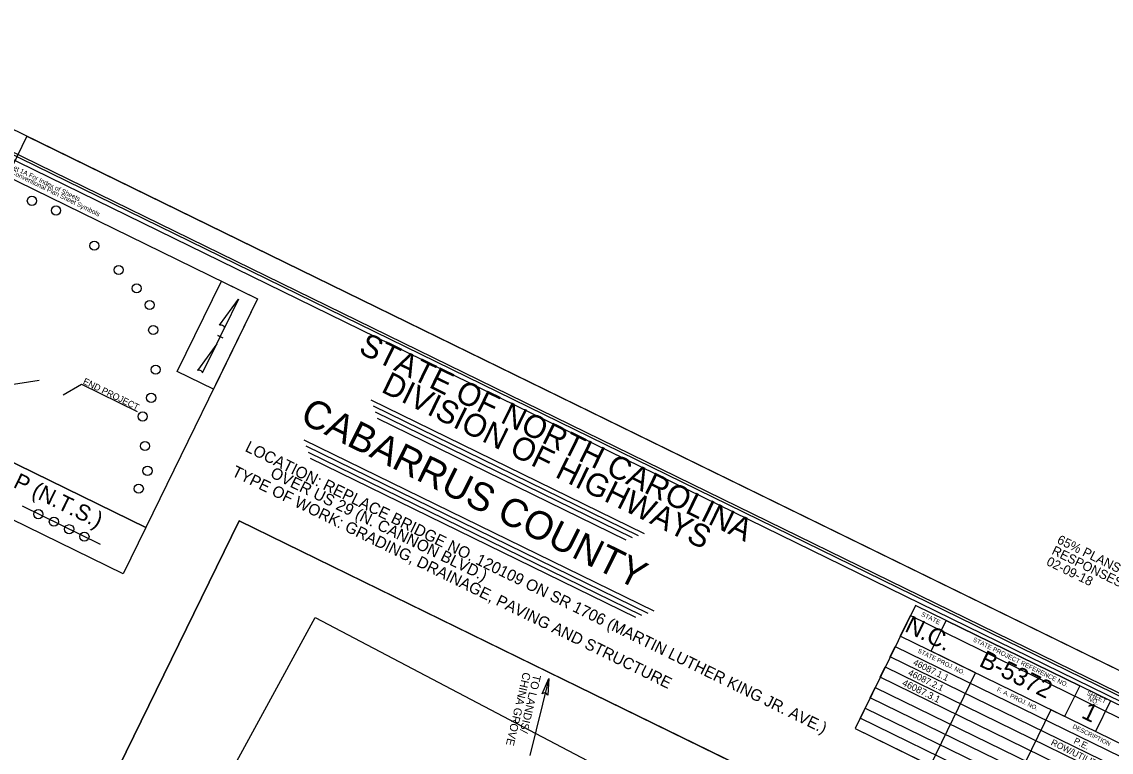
# Model space of a CAD drawing. Extents: x 1517888 to 1526099, y 633375 to 640181.
# Drawn here: x 1519355 to 1521738, y 638583 to 640181 of the extents above; entities that cross this region are included whole.
import ezdxf

# ---------------------------------------------------------------- set-up
doc = ezdxf.new("R2010")
doc.units = 0
for name, color, linetype in [('Default', 7, 'Continuous'), ('Prop North Arrow for Plan Sheets CELL', 7, 'Continuous'), ('Prop Terminator CELL', 7, 'Continuous'), ('Scratch_Level_0', 7, 'Continuous'), ('Sheet Clip Boundary CELL', 7, 'Continuous'), ('Sheet Cutting Line CELL', 7, 'Continuous'), ('Sheet Data Field CELL', 7, 'Continuous'), ('Sheet Plot Border Inside CELL', 7, 'Continuous'), ('Sheet Plot Border Outside CELL', 7, 'Continuous'), ('Sheet Title CELL', 7, 'Continuous')]:
    doc.layers.add(name, color=color, linetype=linetype)

msp = doc.modelspace()

# ---------------------------------------------------------------- linework, layer by layer
at = {"layer": 'Prop North Arrow for Plan Sheets CELL'}
for p, q in [((1519787.8, 639517.2), (1519829.4, 639574.3)), ((1519829.4, 639574.3), (1519797.9, 639509.8)), ((1519829.4, 639574.3), (1519829.4, 639574.3)), ((1519829.4, 639574.3), (1519829.4, 639574.3)), ((1519781.6, 639476.4), (1519798.9, 639511.7)), ((1519797.9, 639509.8), (1519798.8, 639511.7)), ((1519783.9, 639494.7), (1519783.8, 639494.7)), ((1519783.9, 639494.7), (1519794.7, 639489.4)), ((1519788.6, 639492.4), (1519783.9, 639494.7)), ((1519781.6, 639476.4), (1519739.2, 639418.3)), ((1519750.7, 639413), (1519781.6, 639476.4))]:
    msp.add_line(p, q, dxfattribs=at)
for centre, start_param, end_param in [((1519793, 639513.8), 0.216388, 2.908219), ((1519744.8, 639415.3), 0.201328, 3.141593)]:
    msp.add_ellipse(centre, major_axis=(5.68, -2.83), ratio=0.461098, start_param=start_param, end_param=end_param, dxfattribs=at)
at = {"layer": 'Prop Terminator CELL'}
msp.add_lwpolyline([(1520493.1, 638711), (1520507.8, 638744.4), (1520505.3, 638707.8), (1520500.2, 638713.8)], close=True, dxfattribs=at)
at = {"layer": 'Scratch_Level_0'}
msp.add_lwpolyline([(1519830.7, 639089.6), (1521178.1, 638430.5), (1520716.8, 637487.3), (1519369.3, 638146.3)], close=True, dxfattribs=at)
at = {"layer": 'Sheet Clip Boundary CELL'}
msp.add_lwpolyline([(1519997.2, 638878.2), (1520677.9, 638519.7), (1521000.4, 638385.3), (1521102.7, 638308.6), (1521171, 638278.9), (1521396, 638166), (1521492.2, 638121.5), (1521760.4, 637993.1), (1521455.7, 637316.3), (1521359.7, 637143.3), (1520290, 637647.3), (1519534.4, 638030.1)], close=True, dxfattribs=at)
at = {"layer": 'Sheet Cutting Line CELL'}
for q in [(1518399.9, 637954.2), (1522392, 638450.7)]:
    msp.add_line((1519366.5, 639930.5), q, dxfattribs=at)
at = {"layer": 'Sheet Data Field CELL'}
for p, q in [((1519313.6, 639384.5), (1519393.4, 639397.1)), ((1519445.5, 639364.7), (1519486.1, 639388.1)), ((1519486.1, 639388.1), (1519607.9, 639328.5)), ((1519356.1, 639121.8), (1519526.5, 639038.5)), ((1520507.8, 638744.4), (1520466, 638575.9))]:
    msp.add_line(p, q, dxfattribs=at)
for points in [[(1519276.2, 639865.9), (1519871, 639575), (1519626.2, 639074.5), (1519031.4, 639365.4)], [(1519792.1, 639613.6), (1519871, 639575), (1519774.2, 639377.1), (1519695.3, 639415.6)], [(1519031.4, 639365.4), (1519626.2, 639074.5), (1519577, 638973.7), (1518982.1, 639264.6)]]:
    msp.add_lwpolyline(points, close=True, dxfattribs=at)
for centre in [(1519377.4, 639789.3), (1519430.2, 639768), (1519513.8, 639691), (1519567, 639638), (1519606.7, 639597.8), (1519634.8, 639561.5), (1519642.7, 639506.6), (1519648.1, 639420), (1519638.2, 639358.4), (1519619.5, 639317.5), (1519624.6, 639252.8), (1519630.2, 639198.7), (1519611.1, 639159.6), (1519391.3, 639104), (1519425.5, 639087.3), (1519458.9, 639071), (1519492.3, 639054.7)]:
    msp.add_circle(centre, 10, dxfattribs=at)
at = {"layer": 'Sheet Plot Border Inside CELL'}
msp.add_lwpolyline([(1517931.1, 638233.4), (1520925.2, 636769.1), (1521852.3, 638664.7), (1518858.2, 640129.1)], close=True, dxfattribs=at)
at = {"layer": 'Sheet Plot Border Outside CELL'}
msp.add_lwpolyline([(1521880.1, 638701.1), (1518854.6, 640180.8), (1517888, 638204.5), (1520913.6, 636724.8)], close=True, dxfattribs=at)
at = {"layer": 'Sheet Title CELL'}
for p, q in [((1520118.8, 639354.3), (1520716.6, 639061.9)), ((1520123.4, 639340.9), (1520703.2, 639057.3)), ((1520128, 639327.5), (1520689.9, 639052.7)), ((1520132.5, 639314.1), (1520676.5, 639048.1)), ((1519972.1, 639266.6), (1520737.4, 638892.3)), ((1519976.6, 639253.2), (1520724, 638887.7)), ((1519981.2, 639239.8), (1520710.7, 638883.1)), ((1519985.8, 639226.5), (1520697.3, 638878.5))]:
    msp.add_line(p, q, dxfattribs=at)
for points in [[(1521809.7, 638679.9), (1519150.6, 639980.4)], [(1521796.3, 638675.3), (1519245.1, 639923.1)], [(1520477.5, 638773.2), (1519830.7, 639089.6), (1519418.9, 638247.6)], [(1521803.5, 638662.9), (1521309.5, 638904.5), (1521177.7, 638635), (1521342.3, 638554.5), (1521441.2, 638756.6), (1521343.9, 638804.2), (1521376.8, 638871.6), (1521668.8, 638728.7), (1521635.8, 638661.4), (1521605.8, 638676.1), (1521507, 638474), (1521671.7, 638393.4), (1521803.5, 638662.9), (1521736.2, 638695.8), (1521703.2, 638628.4)], [(1521770.6, 638595.5), (1521276.5, 638837.1), (1521298.5, 638882.1), (1521792.6, 638640.4)], [(1521177.7, 638635), (1521671.7, 638393.4), (1521682.7, 638415.8), (1521188.6, 638657.5), (1521199.6, 638679.9), (1521693.7, 638438.3), (1521704.7, 638460.7), (1521210.6, 638702.4), (1521221.6, 638724.9), (1521715.7, 638483.2), (1521726.7, 638505.7), (1521232.6, 638747.3), (1521243.5, 638769.8), (1521737.6, 638528.1), (1521748.6, 638550.6), (1521254.5, 638792.2), (1521265.5, 638814.7), (1521759.6, 638573)], [(1521080.8, 638231.4), (1521178.2, 638430.5), (1520477.5, 638773.2)]]:
    msp.add_lwpolyline(points, dxfattribs=at)

# ---------------------------------------------------------------- texts
at = {"layer": 'Default'}
msp.add_text('END PROJECT', height=14.158, rotation=333.6582, dxfattribs=at).set_placement((1519487.8, 639389.7))
at = {"layer": 'Sheet Data Field CELL'}
for s, height, rotation, p in [('CABARRUS COUNTY', 61.55, 333.6026, (1519960.8, 639306.2)), ('VICINITY MAP (N.T.S.)', 35, 333.9377, (1519082.4, 639287.3)), ('65% PLANS', 20.23, 333.9377, (1521617.5, 639041.2)), ('RESPONSES RESUBMITTAL', 20.23, 333.9377, (1521605.9, 639017.4)), ('02-09-18', 20.23, 333.9377, (1521594.2, 638993.6)), ('46087.1.1', 14, 333.9377, (1521303.2, 638775)), ('CHINA GROVE', 17.5, 256.6772, (1520451.6, 638759.3)), ('TO LANDIS/', 17.5, 256.6772, (1520473.9, 638754.1)), ('46087.2.1', 14, 333.9377, (1521292.2, 638752.5)), ('46087.3.1', 15, 333.9377, (1521279.2, 638730)), ('ROW/UTILITY', 14, 333.9377, (1521604.5, 638599.9)), ('P.E.', 14, 333.9377, (1521654.2, 638603.4))]:
    msp.add_text(s, height=height, rotation=rotation, dxfattribs=at).set_placement(p)
at = {"layer": 'Sheet Title CELL'}
for s, height, p in [('            See Sheet 1B For Conventional Plan Sheet Symbols', 10.241, (1519184.3, 639920.3)), ('  See Sheet 1A For Index of Sheets', 10.241, (1519280.3, 639885.5)), ('STATE OF NORTH CAROLINA', 50, (1520089.6, 639457.5)), ('DIVISION OF HIGHWAYS', 50, (1520138.9, 639372.2)), ('LOCATION: REPLACE BRIDGE NO. 120109 ON SR 1706 (MARTIN LUTHER KING JR. AVE.) ', 25, (1519841.7, 639242.5)), ('TYPE OF WORK: GRADING, DRAINAGE, PAVING AND STRUCTURE', 25, (1519812.8, 639188.8)), ('        OVER US 29 (N. CANNON BLVD.)', 25, (1519829.9, 639218.5)), ('STATE', 10, (1521321.1, 638881.6)), ('N.C.', 38.7, (1521283.9, 638848.8)), ('STATE PROJECT REFERENCE NO.', 10, (1521434, 638826.3)), ('STATE PROJ. NO.', 9.6, (1521313.7, 638801.9)), ('B-5372', 38.7, (1521446.5, 638772.9)), ('F. A. PROJ. NO.', 9.6, (1521486.7, 638717.3)), ('SHEET', 10, (1521682.7, 638709.7)), ('NO.', 10, (1521685.8, 638697.2)), ('1', 38.7, (1521670.3, 638659.8)), ('DESCRIPTION', 9.6, (1521652.2, 638636.3))]:
    msp.add_text(s, height=height, rotation=333.9377, dxfattribs=at).set_placement(p)

doc.saveas('drawing.dxf')
